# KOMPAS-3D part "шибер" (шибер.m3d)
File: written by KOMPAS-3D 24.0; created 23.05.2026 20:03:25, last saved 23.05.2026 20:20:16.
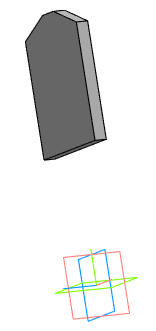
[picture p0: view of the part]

Document properties: Автор: R2D2; Полное имя файла: E:\Работа\Зайцев\GVKR1331E-1W-Fb-2P Задвижка шиберная DN.ru Ду50-300 Ру16-10-6\исходные материалы\DN80\шибер.m3d

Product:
- Part/product: шибер
    Масса: 0.384551
    Раздел спецификации: Прочие изделия
    Примечание: D040-08800

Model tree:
1. Эскиз:5  (with: Ребро.Элемент выдавливания:15, Ребро.Элемент выдавливания:2, Ребро.Элемент выдавливания:1)
2. Элемент выдавливания:6
     Расстояние 1 = 10

Referenced files in E:\Работа\Зайцев\GVKR1331E-1W-Fb-2P Задвижка шиберная DN.ru Ду50-300 Ру16-10-6\исходные материалы\DN80\: GVKR1331E-1W-Fb-2P Задвижка шиберная с выдвижным штоком DN.ru Ду80 Ру16.a3d
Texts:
  Затвор дисковый DN.ru Ду Ру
